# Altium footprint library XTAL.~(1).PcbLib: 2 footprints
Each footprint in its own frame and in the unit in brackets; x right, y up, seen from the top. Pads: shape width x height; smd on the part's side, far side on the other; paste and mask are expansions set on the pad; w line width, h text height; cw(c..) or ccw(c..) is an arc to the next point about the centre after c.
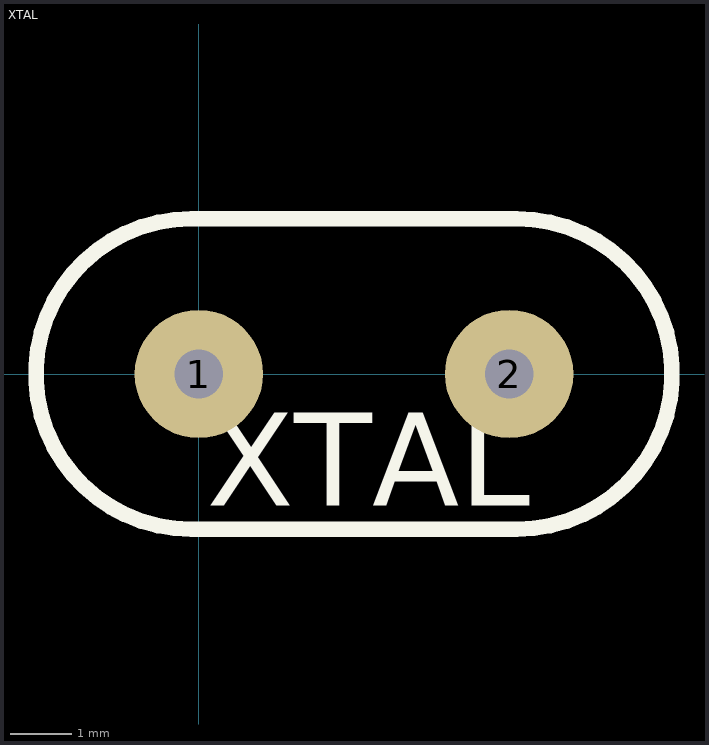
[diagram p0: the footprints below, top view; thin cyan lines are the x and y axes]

## PCBComponent_1 [mm]

## XTAL [mm]
pads (2):
  round 2.1 hole 0.8: 1(0,0) 2(5.08,0)
Top Overlay:
  lines w0.254: -0.127,-2.54 cw(c-0.127,0) -0.127,2.54 5.207,2.54 cw(c5.207,0) 5.207,-2.54 -0.127,-2.54
  text "XTAL" at 0.127,-2.159 h1.52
